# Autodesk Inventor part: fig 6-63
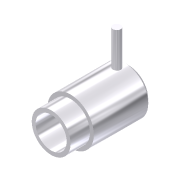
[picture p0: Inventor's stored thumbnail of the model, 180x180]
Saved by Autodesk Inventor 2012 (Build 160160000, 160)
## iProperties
Shininess: 77.0
Angle Display Precision: 2
Document Length Units: 11269
Document Angle Units: 11279
Document Time Units: 11290
Document Mass Units: 11283
Document Length Units Precision: 3
Document Angle Units Precision: 2
Compacted: True
Created: 2001-12
Part Number: fig 6-63
Document SubType Name: Modeling
Designer: Renu Muthoo
Density: 1 g/cm^3
Material: Default
Density: 0.0
Volumn: 0.0
Area: 0.0
PropertySet Name: Model Information
Control State: 0
Master: False
Checked Out: False
Author: Renu Muthoo
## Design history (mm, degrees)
sketch "Sketch2"
  geometry: L1 (-9.573, -4.327)-(-9.573, -5.327); L2 (-9.573, -5.327)-(-4.573, -5.327); L3 (-4.573, -5.327)-(-4.573, -6.327); L4 (-4.573, -6.327)-(9.427, -6.327); L5 (9.427, -6.327)-(10.427, -5.327); L6 (10.427, -5.327)-(10.427, -4.327); L7 (10.427, -4.327)-(-9.573, -4.327); L8 (-13.687, -0.327)-(14, -0.327)
  constraints: 16 end point, 5 parallel, 1 perpendicular, 1 vertical
  dimensions: "d9" = 20 distance of L6.end L1.start; "d10" = 5 distance of L1.end L2.end; "d11" = 12 diameter of L4 L8; "d12" = 10 diameter of L2 L8; "d13" = 8 diameter of L7 L8; "d14" = 45 deg angle of L5 L4; "d15" = 1 horizontal distance of L5.end L4.end
revolve "Revolution2" sketch "Sketch2" stored, may be unused: angle "d16" = 90 deg
workplane "Work Plane1"
workplane "Work Plane2"
sketch "Sketch3"
  geometry: L1 (-4, 8)-(4, 8) reference; C1 r 1 at (-0.098, 5)
  constraints: 1 centre point
  dimensions: "d18" = 3 distance from line of L1 C1.centre; "d19" = 2 diameter of C1
extrude "Extrusion1" join sketch "Sketch3" distance "d20" = 10; taper "d21" = 0 deg
body "Solid1"
other parameters: "d17" = -1
